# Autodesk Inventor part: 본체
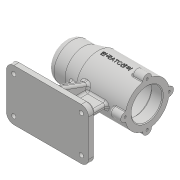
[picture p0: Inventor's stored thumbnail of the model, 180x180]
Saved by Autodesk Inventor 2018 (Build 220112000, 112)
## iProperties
Created: 2019-07
Part Number: 본체
Material: 일반
Document SubType Name: Modeling
Designer: USER
Density: 1 g/cm^3
Appearance: 기본값
Author: USER
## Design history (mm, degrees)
sketch "스케치1"
  geometry: L1 (-46, 35)-(46, 35); L2 (56, 25)-(56, -25); L3 (46, -35)-(-46, -35); L4 (-56, -25)-(-56, 25); L5 (-56, 35)-(56, -35); L6 (56, 35)-(-56, -35); A1 r 10 centre (46, 25) between (56, 25) and (46, 35); A2 r 10 centre (-46, 25) between (-46, 35) and (-56, 25); A3 r 10 centre (-46, -25) between (-56, -25) and (-46, -35); A4 r 10 centre (46, -25) between (46, -35) and (56, -25); 1 further point
  constraints: 12 end point, 8 point on circle, 8 point on line, 8 tangent, 4 centre point, 3 equal radius, 2 midpoint, 2 parallel, 1 horizontal, 1 perpendicular
  dimensions: "d0" = 70 distance of L6.start L5.end; "d1" = 112 distance of L5.start L6.start; "d2" = 10 radius of A1
extrude "돌출1" new body sketch "스케치1" distance "d3" = 10; taper "d4" = 0 deg
sketch "스케치2"
  geometry: L1 (-46, -25)-(46, -25); L2 (46, -25)-(46, 25); L3 (46, 25)-(-46, 25); L4 (-46, 25)-(-46, -25); L5 (-46, -25)-(46, 25); L6 (46, -25)-(-46, 25); L7 (0, 35)-(0, -35); L8 (-56, 0)-(56, 0); C1 r 3 at (-46, 25); C2 r 3 at (46, 25); C3 r 3 at (-46, -25); C4 r 3 at (46, -25); 1 further point
  constraints: 16 end point, 4 centre point, 3 symmetric about line, 2 midpoint, 2 parallel, 1 coincident, 1 horizontal, 1 perpendicular, 3 other
  dimensions: "d5" = 92 distance of L2.end L3.end; "d6" = 50 distance of L1.end L2.end; "d7" = 6 diameter of C1
extrude "돌출2" cut sketch "스케치2" distance "d8" = 10; taper "d9" = 0 deg
chamfer "모따기1" distance "d10" = 3; stored, may be unused: second distance "d11" = 2, angle "d12" = 45 deg
sketch "스케치3"
  geometry: L1 (-56, 80)-(56, 80); L2 (-46, 0)-(46, 0) reference; L3 (56, 0)-(56, 7) reference; L4 (-56, 0)-(-56, 7) reference; L5 (56, 110)-(-11, 110); L6 (-11, 110)-(-31, 105); L7 (-31, 105)-(-46, 105); L8 (-56, 95)-(-56, 80); L9 (-47, 90.5)-(-47, 95.7); L10 (-46.7, 96)-(-43, 96); L11 (-43, 96)-(-43, 97.2); L12 (-42.7, 97.5)-(-25, 97.5); L13 (-25, 97.5)-(-25, 100.7); L14 (56, 110)-(56, 101); L15 (56, 101)-(41, 101); L16 (41, 101)-(41, 101); L17 (38, 104)-(-10, 104); L18 (-13, 101)-(-13, 101); L19 (-24.7, 101)-(-13, 101); L20 (-56, 80)-(-50, 80); L21 (-50, 80)-(-50, 87.5); L22 (-47, 90.5)-(-47, 90.5); A1 r 0.3 centre (-46.7, 95.7) between (-46.7, 96) and (-47, 95.7); A2 r 0.3 centre (-42.7, 97.2) between (-42.7, 97.5) and (-43, 97.2); A3 r 0.3 centre (-24.7, 100.7) between (-24.7, 101) and (-25, 100.7); A4 r 10 centre (-46, 95) between (-46, 105) and (-56, 95); A5 r 3 centre (-47, 87.5) between (-47, 90.5) and (-50, 87.5); A6 r 3 centre (-10, 101) between (-10, 104) and (-13, 101); A7 r 3 centre (38, 101) between (41, 101) and (38, 104); 1 further point
  constraints: 38 end point, 14 point on circle, 14 tangent, 7 centre point, 7 perpendicular, 5 point on line, 4 horizontal, 4 vertical, 3 equal radius, 1 parallel
  dimensions: "d13" = 80 distance between parallel lines of L2 L1; "d14" = 60 diameter of L5 L1; "d15" = 50 diameter of L7 L1; "d16" = 112 distance from line of L8 L5.start; "d17" = 45 distance from line of L8 L5.end; "d18" = 25 distance from line of L8 L6.end; "d19" = 42 diameter of L15 L1; "d20" = 48 diameter of L17 L1; "d21" = 15 distance of L14.end L15.end; "d22" = 54 distance between parallel lines of L16 L18; "d23" = 12 distance between parallel lines of L18 L13; "d24" = 18 distance between parallel lines of L11 L13; "d25" = 4 distance between parallel lines of L9 L11; "d26" = 3 distance between parallel lines of L9 L21; "d27" = 21 diameter of L22 L1; "d28" = 32 diameter of L10 L1; "d29" = 35 diameter of L12 L1; "d30" = 0.3 radius of A1; "d31" = 0.3 radius of A2 (derived); "d32" = 10 radius of A4 (derived); "d33" = 3 radius of A5; "d34" = 42 diameter of L19 L1
revolve "회전1" sketch "스케치3" stored, may be unused: angle "d35" = 90 deg
chamfer "모따기2" distance "d36" = 1; stored, may be unused: second distance "d37" = 2, angle "d38" = 45 deg
sketch "스케치5"
  geometry: L1 (0, 0)-(53, 0); L2 (0, 0)-(0, 32); L3 (-46, 32)-(46, 32) reference; L4 (53, 25)-(53, -25) reference; L5 (56, -25)-(56, 25) reference; L6 (0, -4)-(31, -4); L7 (31, -4)-(31, 4); L8 (31, 4)-(0, 4); L9 (0, 4)-(0, -4); L10 (0, -4)-(31, 4); L11 (31, -4)-(0, 4); 1 further point
  constraints: 16 end point, 4 midpoint, 2 horizontal, 2 parallel, 1 collinear, 1 perpendicular, 1 point on line, 1 vertical
  dimensions: "d41" = 8 distance between parallel lines of L6 L8; "d42" = 25 distance between parallel lines of L5 L7
extrude "돌출3" join sketch "스케치5" stored distance "d43" = 10; taper "d44" = 0 deg
sketch "스케치6"
  geometry: L1 (-46, 10)-(46, 10) reference; L2 (-36, 10)-(-20.57, 52.393); L3 (-56, 0)-(-56, 7) reference; L4 (-56, 65)-(-56, 95) reference; L5 (-46, 105)-(-31, 105) reference; L6 (-31, 105)-(-11, 110) reference; L7 (-11, 110)-(56, 110) reference; L8 (56, 110)-(56, 102) reference; L9 (56, 102)-(55, 101) reference; L10 (55, 101)-(41, 101) reference; L11 (38, 104)-(-10, 104) reference; L12 (-13, 101)-(-24.7, 101) reference; L13 (-25, 100.7)-(-25, 97.5) reference; L14 (-25, 97.5)-(-42.7, 97.5) reference; L15 (-43, 97.2)-(-43, 96) reference; L16 (-43, 96)-(-46.7, 96) reference; L17 (-47, 95.7)-(-47, 90.5) reference; L18 (-50, 87.5)-(-50, 72.5) reference; L19 (-47, 69.5)-(-47, 64.3) reference; L20 (-46.7, 64)-(-43, 64) reference; L21 (-43, 64)-(-43, 62.8) reference; L22 (-42.7, 62.5)-(-25, 62.5) reference; L23 (-25, 62.5)-(-25, 59.3) reference; L24 (-24.7, 59)-(-13, 59) reference; L25 (-10, 56)-(38, 56) reference; L26 (41, 59)-(55, 59) reference; L27 (55, 59)-(56, 58) reference; L28 (56, 58)-(56, 50) reference; L29 (56, 50)-(31, 50) reference; L30 (31, 50)-(31, 10) reference; L31 (31, 10)-(53, 10) reference; L32 (53, 10)-(56, 7) reference; L33 (56, 7)-(56, 0) reference; L34 (56, 0)-(-56, 0) reference; L35 (-56, 0)-(-56, 7) reference; L36 (-56, 7)-(-53, 10) reference; L37 (-53, 10)-(0, 10) reference; L38 (0, 10)-(0, 50) reference; L39 (0, 50)-(-11, 50) reference; L40 (-11, 50)-(-31, 55) reference; L41 (-31, 55)-(-46, 55) reference; A1 r 10 centre (-46, 95) between (-46, 105) and (-56, 95) reference; A2 r 3 centre (38, 101) between (41, 101) and (38, 104) reference; A3 r 3 centre (-10, 101) between (-10, 104) and (-13, 101) reference; A4 r 0.3 centre (-24.7, 100.7) between (-24.7, 101) and (-25, 100.7) reference; A5 r 0.3 centre (-42.7, 97.2) between (-42.7, 97.5) and (-43, 97.2) reference; A6 r 0.3 centre (-46.7, 95.7) between (-46.7, 96) and (-47, 95.7) reference; A7 r 3 centre (-47, 87.5) between (-47, 90.5) and (-50, 87.5) reference; A8 r 3 centre (-47, 72.5) between (-50, 72.5) and (-47, 69.5) reference; A9 r 0.3 centre (-46.7, 64.3) between (-47, 64.3) and (-46.7, 64) reference; A10 r 0.3 centre (-42.7, 62.8) between (-43, 62.8) and (-42.7, 62.5) reference; A11 r 0.3 centre (-24.7, 59.3) between (-25, 59.3) and (-24.7, 59) reference; A12 r 3 centre (-10, 59) between (-13, 59) and (-10, 56) reference; A13 r 3 centre (38, 59) between (38, 56) and (41, 59) reference; A14 r 10 centre (-46, 65) between (-56, 65) and (-46, 55) reference; 1 further point
  constraints: 2 end point, 2 point on line
  dimensions: "d45" = 20 distance from line of L3 L2.start; "d46" = 110 deg angle of L1 L2
feature "리브1" sketch "스케치6" dims "d47" = 1, "d48" = 8, "d49" = 0, "d50" = 0, "d51" = 1, "d52" = 1
sketch "스케치7"
  geometry: L1 (10, 25)-(10, -25) reference; L2 (10, 28)-(52.708, 12.456); L3 (0, 0)-(80, 0); L4 (0, 35)-(7, 35) reference; 1 further point
  constraints: 4 end point, 1 coincident, 1 horizontal, 1 point on line, 2 other
  dimensions: "d53" = 7 distance from line of L4 L2.start; "d54" = 110 deg angle of L1 L2
feature "리브2" sketch "스케치7" dims "d55" = 1, "d56" = 8, "d57" = 0, "d58" = 0, "d59" = 1, "d60" = 1
fillet "모깎기1" dims "d61" = 3
sketch "스케치9"
  geometry: L1 (0, 0)-(0, 30); C1 r 6 at (0, 30); 1 further point
  constraints: 2 end point, 1 centre point, 1 vertical, 1 vertical alignment, 1 other
  dimensions: "d68" = 12 diameter of C1
extrude "돌출4" join sketch "스케치9" distance "d69" = 16; taper "d70" = 0 deg
fillet "모깎기2" dims "d71" = 3
fillet "모깎기3" dims "d72" = 1
sketch "스케치11"
  geometry: A1 r 30 centre (0, -30) between (2.779, -0.129) and (-2.779, -0.129) reference; 2 further points
  constraints: 1 point on circle
hole "구멍1" sketch "스케치11" at (0, 0) diameter "d73" = 3.242; stored, may be unused: countersink angle "d77" = 90 deg, drill point angle "d79" = 118 deg; dims "d74" = 8, "d75" = 4, "d76" = 2, "d78" = 11
node "작업 평면1"
sketch "스케치12"
  geometry: L1 (-78.5, -15)-(-78.5, 15) reference; L2 (-78.5, 0)-(33.5, 0); L3 (33.5, -22)-(33.5, 22) reference; 2 further points
  constraints: 2 end point, 2 midpoint, 1 point on line, 1 other
  dimensions: "d83" = 42 distance from line of point (-8.5, 0) L3
feature "엠보싱1" sketch "스케치12" dims "d5" = 92, "d6" = 50, "d7" = 6, "d84" = 0.5, "d85" = 0
node "솔리드1"
mirror "미러1"
pattern_circular "원형 패턴1" dims "d81" = 360 deg
node "절단 모서리 투영1"
